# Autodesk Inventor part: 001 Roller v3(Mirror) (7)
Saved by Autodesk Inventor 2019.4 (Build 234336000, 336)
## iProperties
Created: 2020-06
Part Number: 001 Roller v3(Mirror) (7)
Material: Generic
Document SubType Name: Modeling
Designer: Administrator
Density: 1 g/cm^3
Appearance: Default
Title: 001 Roller v3(Mirror) (7)
Author: Administrator
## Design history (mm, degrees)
